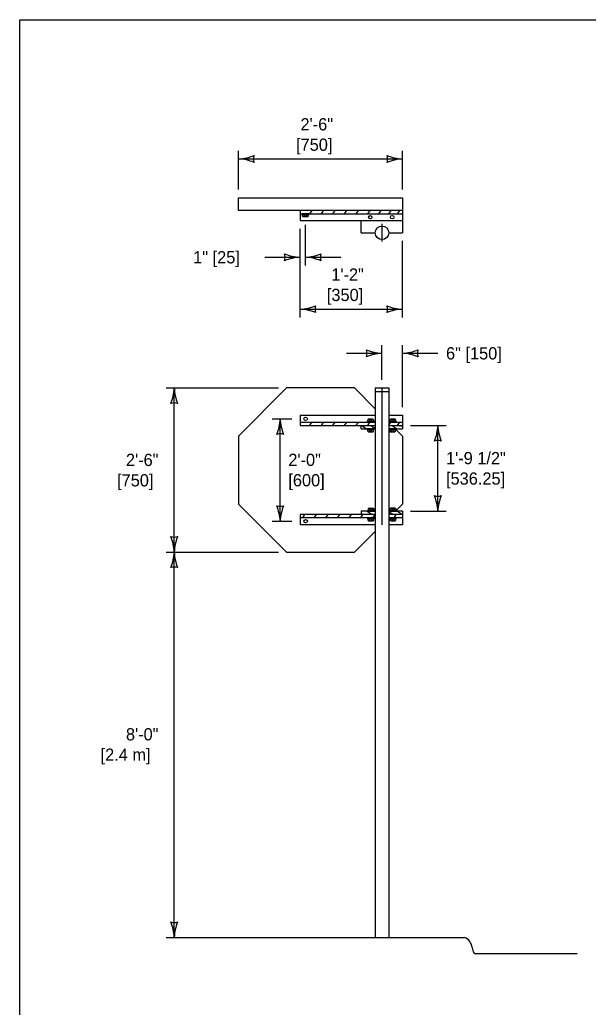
# Model space of a CAD drawing. Extents: x 49991.4 to 50021, y 49987.6 to 50011.4.
# Drawn here: x 49999.384 to 50002.173, y 49994.159 to 49998.999 of the extents above; entities that cross this region are included whole.
import ezdxf

# ---------------------------------------------------------------- set-up
doc = ezdxf.new("R2010")
doc.units = 0
for name, color, linetype in [('Level 1', 7, 'Continuous'), ('Level 2', 7, 'Continuous'), ('Level 3', 7, 'Continuous'), ('Level 4', 7, 'Continuous'), ('Level 5', 7, 'Continuous')]:
    doc.layers.add(name, color=color, linetype=linetype)

msp = doc.modelspace()

# ---------------------------------------------------------------- linework, layer by layer
at = {"layer": 'Level 1'}
for p, q in [((50000.4569, 49998.0647), (50000.4569, 49998.1268)), ((50000.4569, 49998.1268), (50001.2613, 49998.1268)), ((50001.2613, 49998.1268), (50001.261, 49998.0647)), ((50000.7587, 49998.0647), (50000.4569, 49998.0647)), ((50000.7587, 49998.0647), (50000.7587, 49998.0147)), ((50001.261, 49998.0647), (50000.7587, 49998.0647)), ((50000.8062, 49998.048), (50000.8176, 49998.0647)), ((50000.8631, 49998.048), (50000.8745, 49998.0647)), ((50000.92, 49998.048), (50000.9313, 49998.0647)), ((50000.9769, 49998.048), (50000.9882, 49998.0647)), ((50001.0338, 49998.048), (50001.0451, 49998.0647)), ((50001.0906, 49998.048), (50001.1019, 49998.0647)), ((50001.1456, 49998.048), (50001.1568, 49998.0647)), ((50001.1936, 49998.048), (50001.2049, 49998.0647)), ((50001.2366, 49998.048), (50001.2479, 49998.0647)), ((50001.261, 49998.0647), (50001.261, 49997.9549)), ((50000.7587, 49998.048), (50001.1268, 49998.048)), ((50000.7587, 49998.0147), (50001.0584, 49998.0147)), ((50000.7713, 49998.037), (50000.7713, 49998.0433)), ((50000.7739, 49998.0344), (50000.7965, 49998.0344)), ((50000.7805, 49998.0369), (50000.7805, 49998.0433)), ((50000.7897, 49998.0369), (50000.7897, 49998.0433)), ((50000.799, 49998.0364), (50000.799, 49998.0433)), ((50001.0584, 49997.9549), (50001.0584, 49998.0147)), ((50001.0584, 49998.0147), (50001.1933, 49998.0147)), ((50001.1268, 49998.048), (50001.261, 49998.048)), ((50001.1933, 49998.0147), (50001.261, 49998.0147)), ((50001.0584, 49997.9549), (50001.1271, 49997.9549)), ((50001.1936, 49997.9549), (50001.261, 49997.9549)), ((50000.6925, 49997.1942), (50000.4569, 49996.9586)), ((50001.0257, 49997.1942), (50000.6925, 49997.1942)), ((50001.1272, 49997.0928), (50001.0257, 49997.1942)), ((50001.1272, 49997.1942), (50001.1937, 49997.1942)), ((50001.1272, 49997.1942), (50001.1272, 49994.5009)), ((50001.1937, 49997.1942), (50001.1937, 49994.5009)), ((50001.1272, 49997.1776), (50001.1937, 49997.1776)), ((50000.759, 49997.0602), (50000.759, 49997.0102)), ((50000.759, 49997.0602), (50001.1262, 49997.0602)), ((50001.0911, 49997.0382), (50001.0911, 49997.032)), ((50001.1162, 49997.0407), (50001.0936, 49997.0407)), ((50001.1163, 49997.0407), (50001.0936, 49997.0407)), ((50001.1004, 49997.0407), (50001.1004, 49997.032)), ((50001.1097, 49997.0407), (50001.1097, 49997.032)), ((50001.1188, 49997.0382), (50001.1188, 49997.032)), ((50001.1936, 49997.0602), (50001.2613, 49997.0602)), ((50001.1994, 49997.0382), (50001.1994, 49997.032)), ((50001.2246, 49997.0408), (50001.202, 49997.0408)), ((50001.2087, 49997.0407), (50001.2087, 49997.032)), ((50001.218, 49997.0407), (50001.218, 49997.032)), ((50001.2271, 49997.0382), (50001.2271, 49997.032)), ((50001.2613, 49997.0602), (50001.2613, 49996.9935)), ((50000.759, 49997.0269), (50001.1268, 49997.0269)), ((50000.759, 49997.0245), (50000.7603, 49997.0264)), ((50000.759, 49997.0102), (50001.0576, 49997.0102)), ((50000.8062, 49997.0102), (50000.8172, 49997.0264)), ((50000.8631, 49997.0102), (50000.8741, 49997.0264)), ((50000.92, 49997.0102), (50000.9309, 49997.0264)), ((50000.9769, 49997.0102), (50000.9878, 49997.0264)), ((50001.0338, 49997.0102), (50001.0447, 49997.0264)), ((50001.0587, 49997.0102), (50001.1272, 49997.0102)), ((50001.0587, 49996.9935), (50001.0587, 49997.0099)), ((50001.0825, 49996.9939), (50001.0587, 49997.0099)), ((50001.0587, 49996.9935), (50001.1272, 49996.9935)), ((50001.0906, 49997.0102), (50001.1015, 49997.0264)), ((50001.0913, 49996.9822), (50001.0913, 49996.9884)), ((50001.1005, 49996.9796), (50001.1005, 49996.9884)), ((50001.1272, 49996.9942), (50001.1037, 49997.0102)), ((50001.1098, 49996.9796), (50001.1098, 49996.9884)), ((50001.119, 49996.9822), (50001.119, 49996.9884)), ((50001.1937, 49997.0269), (50001.2613, 49997.0269)), ((50001.1937, 49997.0103), (50001.2048, 49997.0269)), ((50001.1937, 49997.0102), (50001.2613, 49997.0102)), ((50001.1937, 49996.9935), (50001.2613, 49996.9935)), ((50001.1986, 49996.9823), (50001.1986, 49996.9885)), ((50001.2317, 49996.9935), (50001.207, 49997.0102)), ((50001.2077, 49996.9797), (50001.2077, 49996.9885)), ((50001.217, 49996.9797), (50001.217, 49996.9885)), ((50001.2262, 49996.9823), (50001.2262, 49996.9885)), ((50001.2287, 49996.9913), (50001.2613, 49996.9586)), ((50001.2366, 49997.0102), (50001.2479, 49997.0269)), ((50001.2613, 49997.0041), (50001.2522, 49997.0102)), ((50000.4569, 49996.9586), (50000.4569, 49996.6254)), ((50001.0938, 49996.9796), (50001.1165, 49996.9796)), ((50001.0939, 49996.9796), (50001.1165, 49996.9796)), ((50001.2011, 49996.9797), (50001.2238, 49996.9797)), ((50001.2012, 49996.9797), (50001.2238, 49996.9797)), ((50001.2613, 49996.9586), (50001.2613, 49996.6254)), ((50000.4569, 49996.6254), (50000.6925, 49996.3898)), ((50001.0934, 49996.6017), (50001.0934, 49996.5956)), ((50001.1185, 49996.6043), (50001.0959, 49996.6043)), ((50001.1186, 49996.6043), (50001.0959, 49996.6043)), ((50001.1026, 49996.6043), (50001.1026, 49996.5956)), ((50001.112, 49996.6043), (50001.112, 49996.5956)), ((50001.1211, 49996.6017), (50001.1211, 49996.5956)), ((50001.2007, 49996.6018), (50001.2007, 49996.5957)), ((50001.2258, 49996.6044), (50001.2032, 49996.6044)), ((50001.2259, 49996.6044), (50001.2032, 49996.6044)), ((50001.2099, 49996.6044), (50001.2099, 49996.5957)), ((50001.2192, 49996.6044), (50001.2192, 49996.5957)), ((50001.2283, 49996.6018), (50001.2283, 49996.5957)), ((50001.2613, 49996.6254), (50001.2311, 49996.5952)), ((50000.759, 49996.5738), (50000.759, 49996.5238)), ((50001.0584, 49996.5738), (50000.759, 49996.5738)), ((50001.1272, 49996.5571), (50000.759, 49996.5571)), ((50000.7717, 49996.5571), (50000.7829, 49996.5738)), ((50000.8285, 49996.5571), (50000.8399, 49996.5738)), ((50000.8856, 49996.5571), (50000.8968, 49996.5738)), ((50000.9424, 49996.5571), (50000.9536, 49996.5738)), ((50000.9992, 49996.5571), (50001.0105, 49996.5738)), ((50001.0563, 49996.5571), (50001.0675, 49996.5738)), ((50001.0584, 49996.5905), (50001.0584, 49996.5738)), ((50001.1272, 49996.5905), (50001.0584, 49996.5905)), ((50001.0584, 49996.5799), (50001.0675, 49996.5738)), ((50001.1272, 49996.5738), (50001.0584, 49996.5738)), ((50001.1267, 49996.5738), (50001.0584, 49996.5738)), ((50001.1261, 49996.5571), (50001.0584, 49996.5571)), ((50001.0878, 49996.5906), (50001.1126, 49996.5738)), ((50001.0926, 49996.5459), (50001.0926, 49996.552)), ((50001.1017, 49996.5433), (50001.1017, 49996.552)), ((50001.111, 49996.5433), (50001.111, 49996.552)), ((50001.1261, 49996.5738), (50001.1148, 49996.5571)), ((50001.1202, 49996.5459), (50001.1202, 49996.552)), ((50001.261, 49996.5905), (50001.1937, 49996.5905)), ((50001.1937, 49996.589), (50001.216, 49996.5738)), ((50001.2613, 49996.5738), (50001.1937, 49996.5738)), ((50001.2613, 49996.5571), (50001.1937, 49996.5571)), ((50001.2009, 49996.5459), (50001.2009, 49996.552)), ((50001.21, 49996.5433), (50001.21, 49996.552)), ((50001.2291, 49996.5738), (50001.2182, 49996.5577)), ((50001.2193, 49996.5433), (50001.2193, 49996.552)), ((50001.2285, 49996.5459), (50001.2285, 49996.552)), ((50001.2366, 49996.5905), (50001.2613, 49996.5739)), ((50001.261, 49996.5905), (50001.2613, 49996.5738)), ((50001.2613, 49996.5738), (50001.2613, 49996.5238)), ((50001.1272, 49996.5238), (50000.759, 49996.5238)), ((50001.095, 49996.5433), (50001.1177, 49996.5433)), ((50001.0951, 49996.5433), (50001.1177, 49996.5433)), ((50001.2613, 49996.5238), (50001.1937, 49996.5238)), ((50001.2033, 49996.5433), (50001.226, 49996.5433)), ((50001.2034, 49996.5433), (50001.226, 49996.5433)), ((50001.0257, 49996.3898), (50001.1272, 49996.4913)), ((50000.6925, 49996.3898), (50001.0257, 49996.3898)), ((50000.1014, 49994.5009), (50001.5659, 49994.5009)), ((50001.6179, 49994.4217), (50002.1179, 49994.4217))]:
    msp.add_line(p, q, dxfattribs=at)
for points in [[(49999.3835, 49998.9992), (50016.7501, 49998.9992), (50016.7501, 49987.7988), (49999.3835, 49987.7988)], [(50000.7686, 49998.048), (50000.7686, 49998.0433), (50000.8014, 49998.0433), (50000.8014, 49998.048)], [(50001.0886, 49996.9932), (50001.0886, 49996.9886), (50001.1214, 49996.9886), (50001.1214, 49996.9932)], [(50001.1215, 49997.0271), (50001.1215, 49997.0318), (50001.0887, 49997.0318), (50001.0887, 49997.0271)], [(50001.1958, 49996.9933), (50001.1958, 49996.9887), (50001.2287, 49996.9887), (50001.2287, 49996.9933)], [(50001.2298, 49997.0271), (50001.2298, 49997.0318), (50001.197, 49997.0318), (50001.197, 49997.0271)], [(50001.0898, 49996.5569), (50001.0898, 49996.5522), (50001.1227, 49996.5522), (50001.1227, 49996.5569)], [(50001.1238, 49996.5907), (50001.1238, 49996.5954), (50001.091, 49996.5954), (50001.091, 49996.5907)], [(50001.1981, 49996.5569), (50001.1981, 49996.5522), (50001.231, 49996.5522), (50001.231, 49996.5569)], [(50001.2311, 49996.5908), (50001.2311, 49996.5955), (50001.1982, 49996.5955), (50001.1982, 49996.5908)]]:
    msp.add_lwpolyline(points, close=True, dxfattribs=at)
for centre, radius in [((50001.103, 49998.031), 0.00843), ((50001.2104, 49998.0317), 0.00843), ((50001.1606, 49997.9549), 0.0333), ((50000.7862, 49997.0428), 0.00843), ((50000.7862, 49996.541), 0.00843)]:
    msp.add_circle(centre, radius, dxfattribs=at)
for centre, radius, start, end in [((50000.7739, 49998.037), 0.00257, 179.3945, 270), ((50000.7779, 49998.0369), 0.00257, 283.8238, 0), ((50000.7831, 49998.0369), 0.00257, 180, 256.1762), ((50000.7871, 49998.0369), 0.00257, 283.8237, 0), ((50000.7923, 49998.0369), 0.00257, 180, 256.1763), ((50000.7965, 49998.037), 0.00257, 270, 346.3632), ((50001.0937, 49997.0382), 0.00257, 90, 180), ((50001.0978, 49997.0382), 0.00257, 0, 90), ((50001.1029, 49997.0382), 0.00257, 90, 180), ((50001.107, 49997.0382), 0.00257, 0, 90), ((50001.1121, 49997.0382), 0.00257, 90, 180), ((50001.1162, 49997.0382), 0.00257, 0, 90), ((50001.202, 49997.0382), 0.00257, 90, 180), ((50001.2061, 49997.0382), 0.00257, 0, 90), ((50001.2112, 49997.0382), 0.00257, 90, 180), ((50001.2153, 49997.0382), 0.00257, 0, 90), ((50001.2204, 49997.0382), 0.00257, 90, 180), ((50001.2245, 49997.0382), 0.00257, 0, 90), ((50001.0939, 49996.9822), 0.00257, 180, 270), ((50001.098, 49996.9822), 0.00257, 270, 0), ((50001.1031, 49996.9822), 0.00257, 180, 270), ((50001.1072, 49996.9822), 0.00257, 270, 0), ((50001.1123, 49996.9822), 0.00257, 180, 270), ((50001.1164, 49996.9822), 0.00257, 270, 0), ((50001.2012, 49996.9823), 0.00257, 180, 270), ((50001.2052, 49996.9823), 0.00257, 270, 0), ((50001.2104, 49996.9823), 0.00257, 180, 270), ((50001.2145, 49996.9823), 0.00257, 270, 0), ((50001.2196, 49996.9823), 0.00257, 180, 270), ((50001.2237, 49996.9823), 0.00257, 270, 0), ((50001.096, 49996.6018), 0.00257, 90, 180), ((50001.1001, 49996.6018), 0.00257, 0, 90), ((50001.1052, 49996.6018), 0.00257, 90, 180), ((50001.1093, 49996.6018), 0.00257, 0, 90), ((50001.1144, 49996.6018), 0.00257, 90, 180), ((50001.1185, 49996.6018), 0.00257, 0, 90), ((50001.2033, 49996.6019), 0.00257, 90, 180), ((50001.2073, 49996.6019), 0.00257, 0, 90), ((50001.2125, 49996.6019), 0.00257, 90, 180), ((50001.2165, 49996.6019), 0.00257, 0, 90), ((50001.2217, 49996.6019), 0.00257, 90, 180), ((50001.2257, 49996.6019), 0.00257, 0, 90), ((50001.0952, 49996.5458), 0.00257, 180, 270), ((50001.0992, 49996.5458), 0.00257, 270, 0), ((50001.1044, 49996.5458), 0.00257, 180, 270), ((50001.1084, 49996.5458), 0.00257, 270, 0), ((50001.1136, 49996.5458), 0.00257, 180, 270), ((50001.1176, 49996.5458), 0.00257, 270, 0), ((50001.2035, 49996.5458), 0.00257, 180, 270), ((50001.2075, 49996.5458), 0.00257, 270, 0), ((50001.2127, 49996.5458), 0.00257, 180, 270), ((50001.2167, 49996.5458), 0.00257, 270, 0), ((50001.2219, 49996.5458), 0.00257, 180, 270), ((50001.2259, 49996.5458), 0.00257, 270, 0), ((50001.5422, 49994.4447), 0.061, 5.9118, 67.1491), ((50001.6634, 49994.4573), 0.061, 185.9118, 213.2855)]:
    msp.add_arc(centre, radius, start, end, dxfattribs=at)
msp.add_spline([(50001.6125, 49994.4239), (50001.6138, 49994.423), (50001.6154, 49994.4221), (50001.6179, 49994.4217)], degree=3, dxfattribs=at)
at = {"layer": 'Level 3'}
for p, q in [((50000.4569, 49998.1668), (50000.4569, 49998.3568)), ((50001.2613, 49998.1668), (50001.2613, 49998.3568)), ((50000.4569, 49998.3168), (50001.2613, 49998.3168)), ((50000.7587, 49997.5404), (50000.7587, 49997.9747)), ((50000.785, 49997.7949), (50000.785, 49997.9943)), ((50001.261, 49997.5404), (50001.261, 49997.9149)), ((50000.5853, 49997.8349), (50000.7587, 49997.8349)), ((50000.785, 49997.8349), (50000.9584, 49997.8349)), ((50000.7592, 49997.5804), (50001.261, 49997.5804)), ((50001.1605, 49997.2342), (50001.1605, 49997.4041)), ((50001.2613, 49997.1002), (50001.2613, 49997.4041)), ((50000.9871, 49997.3641), (50001.1605, 49997.3641)), ((50001.2613, 49997.3641), (50001.4347, 49997.3641)), ((50000.1014, 49997.1942), (50000.6525, 49997.1942)), ((50000.1414, 49996.3898), (50000.1414, 49997.1942)), ((50000.6212, 49997.0428), (50000.719, 49997.0428)), ((50000.6612, 49996.541), (50000.6612, 49997.0428)), ((50001.3013, 49997.0102), (50001.4747, 49997.0102)), ((50001.4347, 49996.5905), (50001.4347, 49997.0102)), ((50001.301, 49996.5905), (50001.4747, 49996.5905)), ((50000.6212, 49996.541), (50000.719, 49996.5409)), ((50000.1014, 49996.3898), (50000.6525, 49996.3898)), ((50000.1414, 49994.5009), (50000.1414, 49996.3898))]:
    msp.add_line(p, q, dxfattribs=at)
for centre, radius, start, end in [((50000.4454, 49998.5495), 0.233, 272.8273, 292.0772), ((50000.4477, 49998.0947), 0.2223, 67.456, 87.6395), ((50000.5851, 49998.3168), 0.0548, 162.1388, 197.8612), ((50001.2705, 49998.5389), 0.2223, 247.456, 267.6395), ((50001.1331, 49998.3168), 0.0548, 342.1388, 17.8612), ((50001.2728, 49998.0841), 0.233, 92.8273, 112.0772), ((50000.7679, 49998.057), 0.2223, 247.456, 267.6395), ((50000.6305, 49997.8349), 0.0548, 342.1388, 17.8612), ((50000.7702, 49997.6022), 0.233, 92.8273, 112.0772), ((50000.7735, 49998.0676), 0.233, 272.8273, 292.0772), ((50000.7758, 49997.6128), 0.2223, 67.456, 87.6395), ((50000.9132, 49997.8349), 0.0548, 162.1388, 197.8612), ((50000.7472, 49997.8131), 0.233, 272.8273, 292.0772), ((50000.7495, 49997.3582), 0.2223, 67.456, 87.6395), ((50000.8869, 49997.5804), 0.0548, 162.1388, 197.8612), ((50001.2702, 49997.8025), 0.2223, 247.456, 267.6395), ((50001.1328, 49997.5804), 0.0548, 342.1388, 17.8612), ((50001.2725, 49997.3477), 0.233, 92.8273, 112.0772), ((50001.1697, 49997.5862), 0.2223, 247.456, 267.6395), ((50001.0323, 49997.3641), 0.0548, 342.1388, 17.8612), ((50001.2498, 49997.5968), 0.233, 272.8273, 292.0772), ((50001.3895, 49997.3641), 0.0548, 162.1388, 197.8612), ((50001.172, 49997.1314), 0.233, 92.8273, 112.0772), ((50001.2521, 49997.142), 0.2223, 67.456, 87.6395), ((49999.9193, 49997.2034), 0.2223, 337.456, 357.6395), ((50000.3741, 49997.2057), 0.233, 182.8273, 202.0772), ((50000.1414, 49997.066), 0.0548, 72.1388, 107.8612), ((50000.4391, 49997.052), 0.2223, 337.456, 357.6395), ((50000.8939, 49997.0543), 0.233, 182.8273, 202.0772), ((50001.2126, 49997.0194), 0.2223, 337.456, 357.6395), ((50001.6674, 49997.0217), 0.233, 182.8273, 202.0772), ((50000.6612, 49996.9146), 0.0548, 72.1388, 107.8612), ((50001.4347, 49996.882), 0.0548, 72.1388, 107.8612), ((50001.4347, 49996.7187), 0.0548, 252.1388, 287.8612), ((50001.202, 49996.579), 0.233, 2.8273, 22.0772), ((50001.6568, 49996.5813), 0.2223, 157.456, 177.6395), ((50000.6612, 49996.6692), 0.0548, 252.1388, 287.8612), ((50000.4285, 49996.5295), 0.233, 2.8273, 22.0772), ((50000.8833, 49996.5318), 0.2223, 157.456, 177.6395), ((50000.1414, 49996.518), 0.0548, 252.1388, 287.8612), ((49999.9087, 49996.3783), 0.233, 2.8273, 22.0772), ((50000.3635, 49996.3806), 0.2223, 157.456, 177.6395), ((49999.9193, 49996.399), 0.2223, 337.456, 357.6395), ((50000.3741, 49996.4013), 0.233, 182.8273, 202.0772), ((50000.1414, 49996.2616), 0.0548, 72.1388, 107.8612), ((50000.1414, 49994.6291), 0.0548, 252.1388, 287.8612), ((49999.9087, 49994.4894), 0.233, 2.8273, 22.0772), ((50000.3635, 49994.4917), 0.2223, 157.456, 177.6395)]:
    msp.add_arc(centre, radius, start, end, dxfattribs=at)
at = {"layer": 'Level 4'}
msp.add_line((50001.1605, 49997.1942), (50001.1605, 49996.5238), dxfattribs=at)
at = {"layer": 'Level 5'}
msp.add_line((50001.1605, 49997.9981), (50001.1605, 49997.9116), dxfattribs=at)

# ---------------------------------------------------------------- texts
at = {"layer": 'Level 2'}
for s, p in [('2\'-6"', (50000.7608, 49998.4568)), ('[750]', (50000.739, 49998.3568)), ('1" [25]', (50000.2342, 49997.8049)), ('1\'-2"', (50000.912, 49997.7204)), ('[350]', (50000.8902, 49997.6204)), ('6" [150]', (50001.4747, 49997.3341)), ('2\'-6"', (49999.9045, 49996.8117)), ('2\'-0"', (50000.7012, 49996.8121)), ('1\'-9 1/2"', (50001.4747, 49996.8204)), ('[750]', (49999.861, 49996.7117)), ('[600]', (50000.7012, 49996.7121)), ('[536.25]', (50001.4747, 49996.7204)), ('8\'-0"', (49999.9045, 49995.4668)), ('[2.4 m]', (49999.78, 49995.3668))]:
    msp.add_text(s, height=0.06, dxfattribs=at).set_placement(p)

doc.saveas('drawing.dxf')
